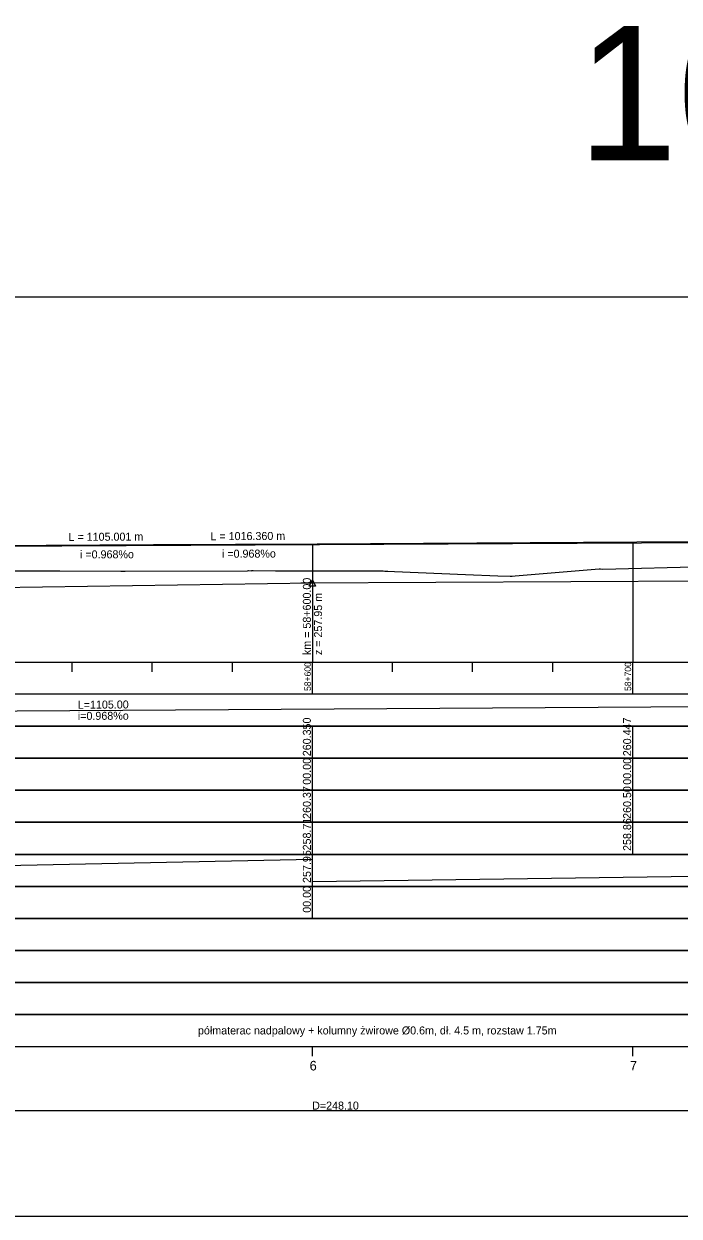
# Model space of a CAD drawing. Extents: x 6445630 to 6518227, y 5499240 to 5511716.
# Drawn here: x 6457741.1 to 6457945.7, y 5508418.3 to 5508790.7 of the extents above; entities that cross this region are included whole.
import ezdxf

# ---------------------------------------------------------------- set-up
doc = ezdxf.new("R2010")
doc.units = 0
for name, color, linetype in [('TOR_PROF-opisy pomocnicze', 7, 'Continuous'), ('TOR_PROF-rowy otwarte', 7, 'Continuous'), ('TOR_PROF-tabelka-geometria T1', 7, 'Continuous'), ('TOR_PROF-tabelka-kilometracja', 7, 'Continuous'), ('TOR_PROF-tabelka-odleglosci T1', 7, 'Continuous'), ('TOR_PROF-tabelka-pochylenia proj T1', 7, 'Continuous'), ('TOR_PROF-tabelka-rodzaj rowu T1', 7, 'Continuous'), ('TOR_PROF-tabelka-rowyT1', 7, 'Continuous'), ('TOR_PROF-tabelka-rurociagi T1', 7, 'Continuous'), ('TOR_PROF-tabelka-rzedne istn T1', 7, 'Continuous'), ('TOR_PROF-tabelka-rzedne proj T1', 7, 'Continuous'), ('TOR_PROF-tabelka-teren istniejacy T1', 7, 'Continuous'), ('TOR_PROF-tabelka-warstwa ochronna T1', 7, 'Continuous'), ('TOR_PROF-tor istniejacy T2', 7, 'Continuous'), ('TOR_PROF-tor projektowany', 7, 'Continuous'), ('TOR_PROF-uklad odniesienia', 7, 'Continuous'), ('TOR_PROF-warstwa ochronna', 7, 'Continuous'), ('TOR_RAMKI-dodatkowe3', 7, 'Continuous'), ('TOR_RAMKI-MASKA WYCIECIA', 7, 'Continuous')]:
    doc.layers.add(name, color=color, linetype=linetype)

msp = doc.modelspace()

# ---------------------------------------------------------------- linework, layer by layer
at = {"layer": 'TOR_PROF-opisy pomocnicze'}
msp.add_line((6457831.21, 5508616.04), (6457831.21, 5508591.29), dxfattribs=at)
msp.add_lwpolyline([(6457831.21, 5508617.04), (6457832.21, 5508615.04), (6457830.21, 5508615.04)], close=True, dxfattribs=at)
at = {"layer": 'TOR_PROF-rowy otwarte'}
for p, q in [((6457827.6, 5508616.04), (6458331.21, 5508618.54)), ((6457492.21, 5508611.29), (6457831.21, 5508616.04))]:
    msp.add_line(p, q, dxfattribs=at)
msp.add_lwpolyline([(6457831.21, 5508616.04), (6457831.21, 5508596.29), (6457831.21, 5508591.29), (6457831.21, 5508591.29)], dxfattribs=at)
at = {"layer": 'TOR_PROF-tabelka-geometria T1'}
for points in [[(6452331.21, 5508451.29), (6453331.21, 5508451.29), (6453331.21, 5508448.62), (6453416.22, 5508448.62), (6453416.22, 5508451.29), (6453496.22, 5508451.29), (6453496.22, 5508453.96), (6453581.21, 5508453.96), (6453581.21, 5508451.29), (6457347.56, 5508451.29), (6457347.56, 5508448.62), (6457429.11, 5508448.62), (6457429.11, 5508451.29), (6457509.11, 5508451.29), (6457509.11, 5508453.96), (6457590.67, 5508453.96), (6457590.67, 5508451.29), (6459780.93, 5508451.29)], [(6452331.21, 5508451.29), (6462731.21, 5508451.29)]]:
    msp.add_lwpolyline(points, dxfattribs=at)
at = {"layer": 'TOR_PROF-tabelka-kilometracja'}
for points in [[(6457831.21, 5508468.29), (6457831.21, 5508471.29)], [(6457931.21, 5508468.29), (6457931.21, 5508471.29)]]:
    msp.add_lwpolyline(points, dxfattribs=at)
at = {"layer": 'TOR_PROF-tabelka-odleglosci T1'}
msp.add_lwpolyline([(6452331.21, 5508551.29), (6462731.21, 5508551.29), (6462731.21, 5508561.29), (6452331.21, 5508561.29)], close=True, dxfattribs=at)
for points in [[(6457831.21, 5508551.29), (6457831.21, 5508561.29)], [(6457931.21, 5508551.29), (6457931.21, 5508561.29)]]:
    msp.add_lwpolyline(points, dxfattribs=at)
at = {"layer": 'TOR_PROF-tabelka-pochylenia proj T1'}
msp.add_lwpolyline([(6452331.21, 5508571.29), (6462731.21, 5508571.29), (6462731.21, 5508581.29), (6452331.21, 5508581.29)], close=True, dxfattribs=at)
msp.add_lwpolyline([(6457211.21, 5508572.79), (6458316.21, 5508579.79)], dxfattribs=at)
at = {"layer": 'TOR_PROF-tabelka-rodzaj rowu T1'}
for points in [[(6452331.21, 5508511.29), (6462731.21, 5508511.29), (6462731.21, 5508521.29), (6452331.21, 5508521.29)], [(6452331.21, 5508511.29), (6462731.21, 5508511.29), (6462731.21, 5508521.29), (6452331.21, 5508521.29)], [(6452331.21, 5508491.29), (6462731.21, 5508491.29), (6462731.21, 5508501.29), (6452331.21, 5508501.29)]]:
    msp.add_lwpolyline(points, close=True, dxfattribs=at)
msp.add_lwpolyline([(6457831.21, 5508511.29), (6457831.21, 5508521.29)], dxfattribs=at)
at = {"layer": 'TOR_PROF-tabelka-rowyT1'}
msp.add_lwpolyline([(6452331.21, 5508521.29), (6462731.21, 5508521.29), (6462731.21, 5508531.29), (6452331.21, 5508531.29)], close=True, dxfattribs=at)
msp.add_lwpolyline([(6452331.21, 5508521.29), (6462731.21, 5508521.29), (6462731.21, 5508531.29), (6452331.21, 5508531.29)], close=True, dxfattribs=at)
msp.add_lwpolyline([(6452331.21, 5508521.29), (6462731.21, 5508521.29), (6462731.21, 5508531.29), (6452331.21, 5508531.29)], close=True, dxfattribs=at)
for points in [[(6457831.21, 5508521.29), (6457831.21, 5508531.29)], [(6457492.21, 5508522.79), (6457831.21, 5508529.79)], [(6457831.21, 5508522.79), (6458331.21, 5508529.79)]]:
    msp.add_lwpolyline(points, dxfattribs=at)
at = {"layer": 'TOR_PROF-tabelka-rurociagi T1'}
msp.add_lwpolyline([(6452331.21, 5508501.29), (6462731.21, 5508501.29), (6462731.21, 5508511.29), (6452331.21, 5508511.29)], close=True, dxfattribs=at)
at = {"layer": 'TOR_PROF-tabelka-rzedne istn T1'}
msp.add_lwpolyline([(6452331.21, 5508541.29), (6462731.21, 5508541.29), (6462731.21, 5508551.29), (6452331.21, 5508551.29)], close=True, dxfattribs=at)
for points in [[(6457831.21, 5508541.29), (6457831.21, 5508551.29)], [(6457931.21, 5508541.29), (6457931.21, 5508551.29)], [(6457831.21, 5508531.29), (6457831.21, 5508541.29)], [(6457831.21, 5508531.29), (6457831.21, 5508541.29)], [(6457831.21, 5508531.29), (6457831.21, 5508541.29)], [(6457831.21, 5508531.29), (6457831.21, 5508541.29)], [(6457931.21, 5508531.29), (6457931.21, 5508541.29)], [(6457931.21, 5508531.29), (6457931.21, 5508541.29)], [(6457931.21, 5508531.29), (6457931.21, 5508541.29)], [(6457931.21, 5508531.29), (6457931.21, 5508541.29)]]:
    msp.add_lwpolyline(points, dxfattribs=at)
at = {"layer": 'TOR_PROF-tabelka-rzedne proj T1'}
msp.add_lwpolyline([(6452331.21, 5508561.29), (6462731.21, 5508561.29), (6462731.21, 5508571.29), (6452331.21, 5508571.29)], close=True, dxfattribs=at)
for points in [[(6457831.21, 5508561.29), (6457831.21, 5508571.29)], [(6457931.21, 5508561.29), (6457931.21, 5508571.29)]]:
    msp.add_lwpolyline(points, dxfattribs=at)
at = {"layer": 'TOR_PROF-tabelka-teren istniejacy T1'}
msp.add_lwpolyline([(6452331.21, 5508531.29), (6462731.21, 5508531.29), (6462731.21, 5508541.29), (6452331.21, 5508541.29)], close=True, dxfattribs=at)
msp.add_lwpolyline([(6452331.21, 5508531.29), (6462731.21, 5508531.29), (6462731.21, 5508541.29), (6452331.21, 5508541.29)], close=True, dxfattribs=at)
msp.add_lwpolyline([(6452331.21, 5508531.29), (6462731.21, 5508531.29), (6462731.21, 5508541.29), (6452331.21, 5508541.29)], close=True, dxfattribs=at)
msp.add_lwpolyline([(6452331.21, 5508531.29), (6462731.21, 5508531.29), (6462731.21, 5508541.29), (6452331.21, 5508541.29)], close=True, dxfattribs=at)
at = {"layer": 'TOR_PROF-tabelka-warstwa ochronna T1'}
msp.add_lwpolyline([(6452331.21, 5508481.29), (6462731.21, 5508481.29), (6462731.21, 5508491.29), (6452331.21, 5508491.29)], close=True, dxfattribs=at)
at = {"layer": 'TOR_PROF-tor istniejacy T2'}
msp.add_lwpolyline([(6457982.42, 5508629.04), (6457932.49, 5508628.79), (6457882.57, 5508628.49), (6457832.68, 5508628.14), (6457781.6, 5508627.94), (6457731.22, 5508627.64), (6457680.54, 5508627.34), (6457629.95, 5508626.94), (6457578.7, 5508626.49), (6457528.26, 5508626.19), (6457480.24, 5508625.79), (6457430.19, 5508625.39), (6457379.85, 5508625.04), (6457331.03, 5508624.69)], dxfattribs=at)
at = {"layer": 'TOR_PROF-tor projektowany'}
for p in [(6457211.21, 5508625.04), (6457299.85, 5508625.47)]:
    msp.add_line(p, (6458316.21, 5508630.39), dxfattribs=at)
for points in [[(6457831.21, 5508628.04), (6457831.21, 5508596.29), (6457831.21, 5508591.29), (6457831.21, 5508591.29)], [(6457831.21, 5508628.04), (6457831.21, 5508596.29), (6457831.21, 5508591.29), (6457831.21, 5508591.29)], [(6457931.21, 5508628.53), (6457931.21, 5508596.29), (6457931.21, 5508591.29), (6457931.21, 5508591.29)], [(6457931.21, 5508628.53), (6457931.21, 5508596.29), (6457931.21, 5508591.29), (6457931.21, 5508591.29)]]:
    msp.add_lwpolyline(points, dxfattribs=at)
at = {"layer": 'TOR_PROF-uklad odniesienia'}
for p, q in [((6452331.21, 5508591.29), (6462731.21, 5508591.29)), ((6452331.21, 5508591.29), (6462731.21, 5508591.29)), ((6457756.21, 5508588.29), (6457756.21, 5508591.29)), ((6457756.21, 5508588.29), (6457756.21, 5508591.29)), ((6457781.21, 5508588.29), (6457781.21, 5508591.29)), ((6457781.21, 5508588.29), (6457781.21, 5508591.29)), ((6457806.21, 5508588.29), (6457806.21, 5508591.29)), ((6457806.21, 5508588.29), (6457806.21, 5508591.29)), ((6457831.21, 5508581.29), (6457831.21, 5508591.29)), ((6457831.21, 5508581.29), (6457831.21, 5508591.29)), ((6457856.21, 5508588.29), (6457856.21, 5508591.29)), ((6457856.21, 5508588.29), (6457856.21, 5508591.29)), ((6457881.21, 5508588.29), (6457881.21, 5508591.29)), ((6457881.21, 5508588.29), (6457881.21, 5508591.29)), ((6457906.21, 5508588.29), (6457906.21, 5508591.29)), ((6457906.21, 5508588.29), (6457906.21, 5508591.29)), ((6457931.21, 5508581.29), (6457931.21, 5508591.29)), ((6457931.21, 5508581.29), (6457931.21, 5508591.29))]:
    msp.add_line(p, q, dxfattribs=at)
at = {"layer": 'TOR_PROF-warstwa ochronna'}
msp.add_lwpolyline([(6452331.21, 5508471.29), (6462731.21, 5508471.29), (6462731.21, 5508481.29), (6452331.21, 5508481.29)], close=True, dxfattribs=at)
at = {"layer": 'TOR_RAMKI-dodatkowe3'}
for p, q in [((6457894.51, 5508618.24), (6457920.73, 5508620.42)), ((6457920.73, 5508620.42), (6457921.09, 5508620.41)), ((6457921.09, 5508620.41), (6457921.85, 5508620.37)), ((6457921.85, 5508620.37), (6457955.62, 5508621.23)), ((6457733.65, 5508619.87), (6457752.38, 5508619.83)), ((6457752.38, 5508619.83), (6457771.39, 5508619.73)), ((6457771.39, 5508619.73), (6457772.15, 5508619.75)), ((6457772.15, 5508619.75), (6457772.38, 5508619.75)), ((6457772.38, 5508619.75), (6457772.76, 5508619.72)), ((6457772.76, 5508619.72), (6457810.91, 5508619.88)), ((6457810.91, 5508619.88), (6457811.24, 5508619.91)), ((6457811.24, 5508619.91), (6457812.03, 5508619.81)), ((6457812.03, 5508619.81), (6457812.25, 5508619.93)), ((6457812.25, 5508619.93), (6457812.72, 5508619.92)), ((6457812.72, 5508619.92), (6457819.72, 5508619.87)), ((6457819.72, 5508619.87), (6457852.93, 5508619.8)), ((6457852.93, 5508619.8), (6457853.26, 5508619.78)), ((6457853.26, 5508619.78), (6457853.77, 5508619.7)), ((6457853.77, 5508619.7), (6457854.7, 5508619.74)), ((6457854.7, 5508619.74), (6457856.84, 5508619.66)), ((6457856.84, 5508619.66), (6457878.98, 5508618.71)), ((6457878.98, 5508618.71), (6457889.13, 5508618.25)), ((6457889.13, 5508618.25), (6457892.98, 5508618.13)), ((6457892.98, 5508618.13), (6457893.59, 5508618.17)), ((6457893.59, 5508618.17), (6457894.51, 5508618.24))]:
    msp.add_line(p, q, dxfattribs=at)
at = {"layer": 'TOR_RAMKI-MASKA WYCIECIA'}
msp.add_lwpolyline([(6457196.67, 5508418.29), (6459246.67, 5508418.29), (6459246.67, 5508705.29), (6457196.67, 5508705.29)], close=True, dxfattribs=at)

# ---------------------------------------------------------------- texts
at = {"layer": 'TOR_PROF-opisy pomocnicze'}
for s, rotation, p in [('L = 1105.001 m', 0.2774, (6457755.06, 5508629.17)), ('L = 1016.360 m', 0.2774, (6457799.38, 5508629.39)), ('  i =0.968%o', 0.2774, (6457756.79, 5508623.68)), ('  i =0.968%o', 0.2774, (6457801.11, 5508623.9)), ('km = 58+600.00', 90, (6457830.71, 5508593.52)), ('z = 257.95 m', 90, (6457834.21, 5508593.52))]:
    msp.add_text(s, height=2.5, rotation=rotation, dxfattribs=at).set_placement(p)
at = {"layer": 'TOR_PROF-tabelka-geometria T1'}
msp.add_text('D=248.10', height=2.5, dxfattribs=at).set_placement((6457831.11, 5508451.57))
at = {"layer": 'TOR_PROF-tabelka-kilometracja'}
for s, p in [('6', (6457830.32, 5508463.79)), ('7', (6457930.32, 5508463.79))]:
    msp.add_text(s, height=3, dxfattribs=at).set_placement(p)
at = {"layer": 'TOR_PROF-tabelka-odleglosci T1'}
for p in [(6457830.71, 5508553.03), (6457930.71, 5508553.03)]:
    msp.add_text('00.00', height=2.5, rotation=90, dxfattribs=at).set_placement(p)
at = {"layer": 'TOR_PROF-tabelka-pochylenia proj T1'}
for s, p in [('L=1105.00', (6457757.95, 5508576.75)), ('i=0.968%o', (6457757.96, 5508573.25))]:
    msp.add_text(s, height=2.5, rotation=0.363, dxfattribs=at).set_placement(p)
at = {"layer": 'TOR_PROF-tabelka-rodzaj rowu T1'}
msp.add_text('00.00', height=2.5, rotation=90, dxfattribs=at).set_placement((6457830.71, 5508513.04))
at = {"layer": 'TOR_PROF-tabelka-rowyT1'}
msp.add_text('257.95', height=2.5, rotation=90, dxfattribs=at).set_placement((6457830.71, 5508522.35))
at = {"layer": 'TOR_PROF-tabelka-rzedne istn T1'}
for s, p in [('260.37', (6457830.71, 5508542.36)), ('260.50', (6457930.71, 5508542.36)), ('258.71', (6457830.71, 5508532.52)), ('258.86', (6457930.71, 5508532.35))]:
    msp.add_text(s, height=2.5, rotation=90, dxfattribs=at).set_placement(p)
at = {"layer": 'TOR_PROF-tabelka-rzedne proj T1'}
for s, p in [('260.350', (6457830.71, 5508561.93)), ('260.447', (6457930.71, 5508561.93))]:
    msp.add_text(s, height=2.5, rotation=90, dxfattribs=at).set_placement(p)
at = {"layer": 'TOR_PROF-uklad odniesienia'}
msp.add_text('10', height=42, dxfattribs=at).set_placement((6457913.96, 5508748.03))
for s, p in [('58+600', (6457830.71, 5508582.31)), ('58+600', (6457830.71, 5508582.31)), ('58+700', (6457930.71, 5508582.31)), ('58+700', (6457930.71, 5508582.31))]:
    msp.add_text(s, height=2, rotation=90, dxfattribs=at).set_placement(p)
at = {"layer": 'TOR_PROF-warstwa ochronna'}
msp.add_text('półmaterac nadpalowy + kolumny żwirowe Ø0.6m, dł. 4.5 m, rozstaw 1.75m', height=2.5, rotation=360, dxfattribs=at).set_placement((6457795.47, 5508475.04))

doc.saveas('drawing.dxf')
